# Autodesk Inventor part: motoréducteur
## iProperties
Shininess: 64.0
Length Units: 11269
Angle Units: 11279
Time Units: 11290
Mass Units: 11283
Length Display Precision: 3
Angle Display Precision: 2
Compacted: True
Part Number: motoréducteur
Document SubType Name: Modeling
Created: 2005-02
Material: Par défaut
Designer: LEGERET Philippe
Density: 0.0
Volumn: 0.0
Area: 0.0
PropertySet Name: Model Information
Control State: 0
Master: False
Checked Out: False
Author: LEGERET Philippe
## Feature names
1. Révolution1 [Revolution]
2. Révolution2 [Revolution]
3. Congé1 [Fillet]
4. Extrusion1
5. Perçage1 [Hole]
6. Réseau circulaire1 [Circular Pattern]
7. Extrusion2
